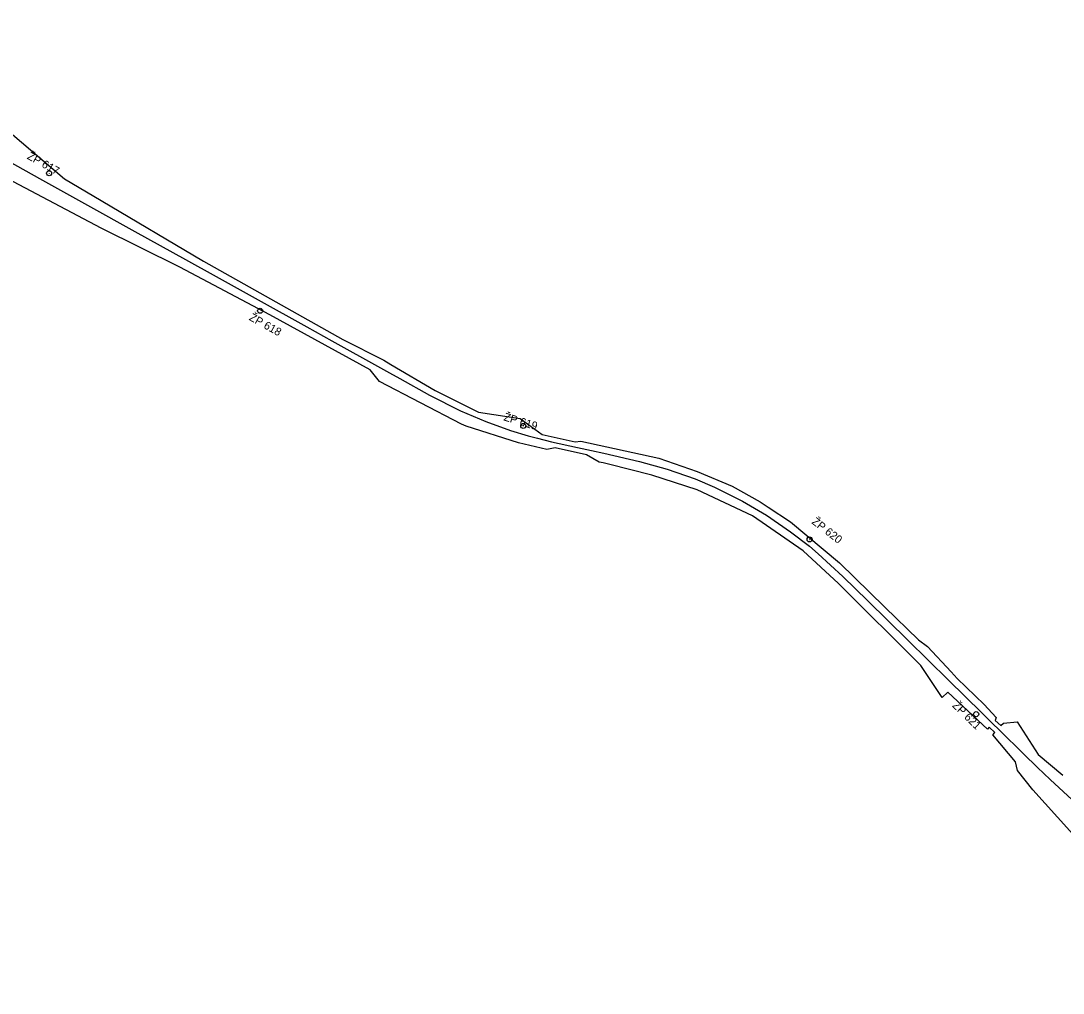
# Model space of a CAD drawing. Extents: x -792643 to -787072, y -1118436 to -1109677.
# Drawn here: x -789940 to -789315, y -1114617 to -1114034 of the extents above; entities that cross this region are included whole.
import ezdxf

# ---------------------------------------------------------------- set-up
doc = ezdxf.new("R2010")
doc.units = 0
for name, color, linetype in [('Vrstva 1', 7, 'Continuous'), ('Vrstva 53', 7, 'Continuous'), ('Vrstva 63', 7, 'Continuous')]:
    doc.layers.add(name, color=color, linetype=linetype)

msp = doc.modelspace()

# ---------------------------------------------------------------- linework, layer by layer
at = {"layer": 'Vrstva 1'}
for points in [[(-789992.89, -1114093.06), (-789966.79, -1114107.53), (-789928.36, -1114128.84), (-789899.61, -1114144.81), (-789871.25, -1114160.56), (-789840.77, -1114177.49), (-789822.44, -1114187.68), (-789797.27, -1114201.65), (-789768.13, -1114217.82), (-789753.19, -1114226.09), (-789723.93, -1114242.34), (-789718.57, -1114245.31), (-789712.31, -1114248.79)], [(-789712.31, -1114248.79), (-789694.52, -1114258.64), (-789676.07, -1114268.04), (-789660.88, -1114274.56), (-789646.01, -1114279.9), (-789635.54, -1114283.04), (-789629.94, -1114284.54), (-789621.51, -1114286.7), (-789605.82, -1114290.08), (-789597.54, -1114291.87)], [(-789597.54, -1114291.87), (-789590.08, -1114293.53)], [(-789590.08, -1114293.53), (-789568.65, -1114298.54), (-789552.22, -1114303.1), (-789535.44, -1114308.95), (-789523.83, -1114313.86), (-789507.01, -1114322.23), (-789492.64, -1114330.66), (-789478.17, -1114340.52), (-789466.89, -1114349.24), (-789461.51, -1114353.77), (-789446.8, -1114367.32), (-789431.93, -1114381.89)], [(-789431.93, -1114381.89), (-789407.88, -1114405.56), (-789383.57, -1114429.41), (-789363.55, -1114449.05), (-789357.41, -1114455.1), (-789352.66, -1114459.75), (-789338.53, -1114473.65)], [(-789338.53, -1114473.65), (-789330.19, -1114481.81), (-789322.58, -1114489.09), (-789309.34, -1114501.13), (-789298.32, -1114510.55), (-789284.69, -1114521.46), (-789270.77, -1114531.83), (-789257.88, -1114540.78), (-789243.27, -1114550.25), (-789228.51, -1114559.09), (-789214.02, -1114567.11), (-789200.11, -1114574.26), (-789184.73, -1114581.5), (-789166.72, -1114589.18), (-789156.33, -1114593.21), (-789141.12, -1114598.67), (-789125.25, -1114603.78), (-789109.13, -1114608.43), (-789091.69, -1114612.82), (-789082.49, -1114614.9), (-789072.68, -1114617.04)]]:
    msp.add_lwpolyline(points, dxfattribs=at)
at = {"layer": 'Vrstva 53'}
for points in [[(-790049.23, -1114034.44), (-790014.82, -1114057.41), (-790011.64, -1114059.53), (-790007.66, -1114062.18), (-790004.95, -1114067.14), (-789993.35, -1114088.34), (-789984.83, -1114079.42), (-789951.34, -1114096.74), (-789913.42, -1114129.06), (-789891.43, -1114142.08), (-789830.15, -1114178.38), (-789746.5, -1114225.43), (-789721.98, -1114237.82), (-789717.72, -1114240.35), (-789691.28, -1114256.01), (-789665.23, -1114268.84), (-789640.19, -1114272.7), (-789627.07, -1114282.33), (-789607.19, -1114286.63), (-789603.91, -1114286.39)], [(-789600.46, -1114294.39), (-789619.3, -1114290.36), (-789624.34, -1114291.37), (-789641.23, -1114287.32), (-789672.68, -1114277.31), (-789675.34, -1114276.11), (-789724.61, -1114250.58), (-789730.23, -1114243.59), (-789790.24, -1114210.69), (-789844.34, -1114181.96), (-789891.39, -1114158.73), (-789943.99, -1114130.82), (-789972.38, -1114117.19), (-789989.47, -1114115.38), (-790009.42, -1114105.25), (-790039.99, -1114089.61), (-790043.48, -1114088.64), (-790052.2, -1114080.82), (-790070.36, -1114064.18)], [(-789603.91, -1114286.39), (-789557.19, -1114296.51), (-789534.19, -1114304.37), (-789513.07, -1114313.2), (-789496.46, -1114322.71), (-789491.56, -1114325.89), (-789478.18, -1114334.57), (-789448.8, -1114359.16), (-789421.56, -1114385.77), (-789401.5, -1114405.4), (-789396.12, -1114409.35), (-789381.93, -1114424.44), (-789378.22, -1114428.46), (-789362.04, -1114444), (-789354.83, -1114451.89), (-789355.6, -1114453.64), (-789352.15, -1114456.75), (-789350.58, -1114455.19), (-789342.35, -1114454.54), (-789329.78, -1114474.08), (-789314.84, -1114486.39)], [(-789332.87, -1114495.13), (-789342.11, -1114483.58), (-789343.4, -1114478.53), (-789356.86, -1114462.31), (-789355.65, -1114460.93), (-789359, -1114457.59), (-789360.15, -1114458.92), (-789383.79, -1114436.65), (-789387.36, -1114439.86), (-789400.13, -1114420.69), (-789449.47, -1114371.56), (-789470.68, -1114352.09), (-789500.91, -1114330.99), (-789534.18, -1114315.38), (-789561.38, -1114306.6), (-789587.26, -1114300.1), (-789590.47, -1114299.37), (-789592.9, -1114298.82), (-789600.46, -1114294.39)], [(-789308.97, -1114521.75), (-789318.04, -1114511.65), (-789332.87, -1114495.13)]]:
    msp.add_lwpolyline(points, dxfattribs=at)
at = {"layer": 'Vrstva 63'}
for p, q in [((-789922.69, -1114125.73), (-789922.52, -1114125.83)), ((-789796.19, -1114208.13), (-789796.01, -1114208.23)), ((-789638.46, -1114277.17), (-789638.26, -1114277.22)), ((-789466.84, -1114345.12), (-789466.69, -1114345.24)), ((-789366.96, -1114449.8), (-789366.82, -1114449.94))]:
    msp.add_line(p, q, dxfattribs=at)
for centre in [(-789922.61, -1114125.78), (-789796.1, -1114208.18), (-789638.36, -1114277.19), (-789466.77, -1114345.18), (-789366.89, -1114449.87)]:
    msp.add_circle(centre, 1.51, dxfattribs=at)

# ---------------------------------------------------------------- texts
for s, rotation, p in [('ŽP 617', 330.9437, (-789936.24, -1114116.88)), ('ŽP 618', 330.97262, (-789803.16, -1114213.49)), ('ŽP 619', 343.29473, (-789650.52, -1114273.75)), ('ŽP 620', 322.28712, (-789465.88, -1114335.32)), ('ŽP 621', 315.53311, (-789381.54, -1114445.06))]:
    msp.add_text(s, height=4.8, rotation=rotation, dxfattribs=at).set_placement(p)

doc.saveas('drawing.dxf')
